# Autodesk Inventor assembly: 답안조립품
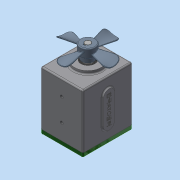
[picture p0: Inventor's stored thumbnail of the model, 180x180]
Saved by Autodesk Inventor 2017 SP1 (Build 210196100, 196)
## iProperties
Part Number: 답안조립품
Material: 일반
Document SubType Name: Assembly
Designer: MRC
Author: MRC
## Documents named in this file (17)
- C:\Users\MRC\Desktop\610205V1008\답안조립품.iam
- C:\Users\MRC\Desktop\610205V1008\본체.ipt
- C:\Users\MRC\Desktop\610205V1008\가변스프링.ipt
- C:\Users\MRC\Desktop\610205V1008\멈춤나사 M3x8.ipt
- C:\Users\MRC\Desktop\610205V1008\메인 기어 축.ipt
- C:\Users\MRC\Desktop\610205V1008\베어링 608.ipt
- C:\Users\MRC\Desktop\610205V1008\베어링 6903.ipt
- C:\Users\MRC\Desktop\610205V1008\볼트 M4 x 10.ipt
- C:\Users\MRC\Desktop\610205V1008\부시.ipt
- C:\Users\MRC\Desktop\610205V1008\서브 기어 축.ipt
- C:\Users\MRC\Desktop\610205V1008\슬라이더.ipt
- C:\Users\MRC\Desktop\610205V1008\오일 실 8 22 7.ipt
- C:\Users\MRC\Desktop\610205V1008\오일 실 17 30 8.ipt
- C:\Users\MRC\Desktop\610205V1008\커버.ipt
- C:\Users\MRC\Desktop\610205V1008\키 5 x 5 x 24.ipt
- C:\Users\MRC\Desktop\610205V1008\팬날개.ipt
- 팬날개.ipt
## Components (1 placed, 1 different names)
1. 가변스프링:1
